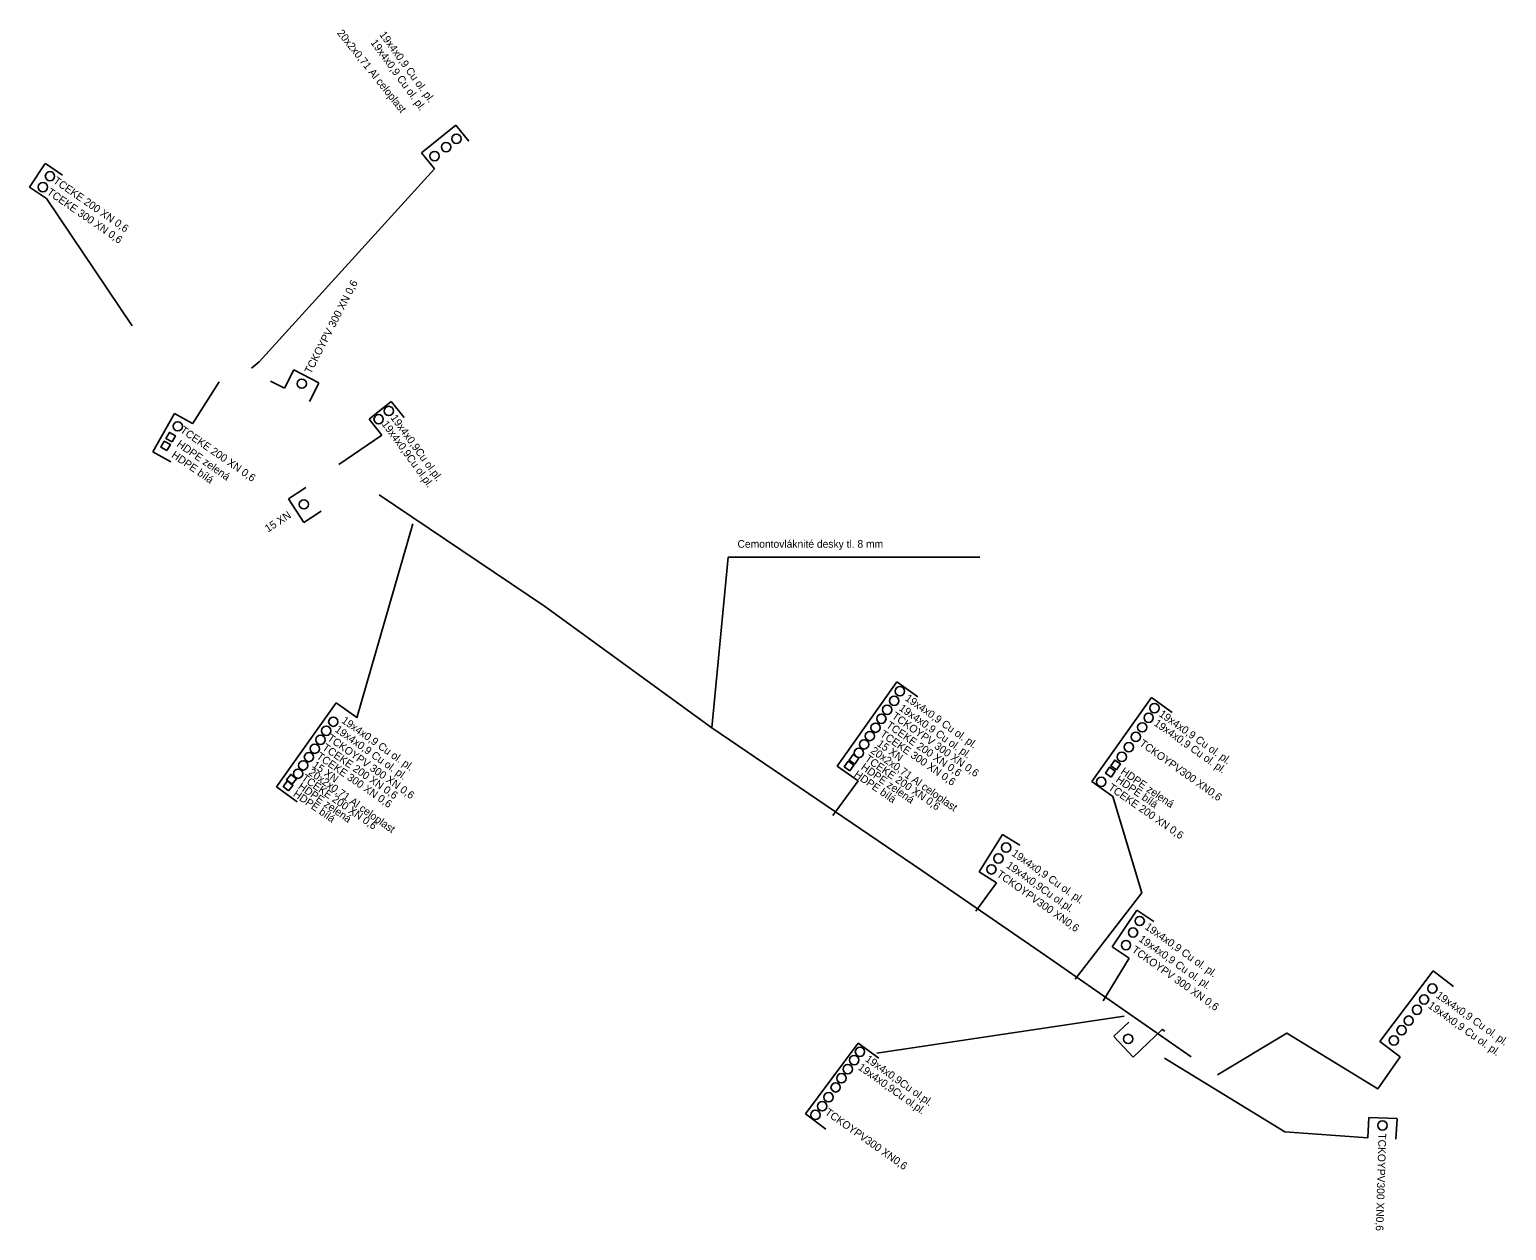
# Model space of a CAD drawing. Extents: x -668939 to -668824, y -1128143 to -1128050.
import ezdxf

# ---------------------------------------------------------------- set-up
doc = ezdxf.new("R2010")
doc.units = 0
doc.layers.add('Vrstva 20', color=7, linetype='Continuous')
doc.layers.add('Vrstva 30', color=7, linetype='Continuous')

msp = doc.modelspace()

# ---------------------------------------------------------------- linework, layer by layer
at = {"layer": 'Vrstva 20'}
for p, q in [((-668905.91, -1128057.19), (-668908.6, -1128059.34)), ((-668904.91, -1128058.43), (-668905.91, -1128057.19)), ((-668908.6, -1128059.34), (-668907.6, -1128060.59)), ((-668937.98, -1128060.18), (-668939.21, -1128062.02)), ((-668936.64, -1128061.08), (-668937.97, -1128060.19)), ((-668939.21, -1128062.02), (-668937.87, -1128062.91)), ((-668919.3, -1128077.73), (-668920.4, -1128077.18)), ((-668918.57, -1128076.3), (-668919.3, -1128077.73)), ((-668916.61, -1128077.31), (-668918.57, -1128076.3)), ((-668917.35, -1128078.75), (-668916.62, -1128077.32)), ((-668910.97, -1128078.75), (-668912.69, -1128080.13)), ((-668909.96, -1128080.01), (-668910.96, -1128078.76)), ((-668912.69, -1128080.13), (-668911.69, -1128081.38)), ((-668911.69, -1128081.38), (-668915.05, -1128083.68)), ((-668917.64, -1128085.47), (-668918.98, -1128086.35)), ((-668918.99, -1128086.36), (-668917.78, -1128088.2)), ((-668917.78, -1128088.2), (-668916.44, -1128087.33)), ((-668852.75, -1128118.47), (-668854.67, -1128121.34)), ((-668851.42, -1128119.36), (-668852.75, -1128118.47)), ((-668855.38, -1128125.56), (-668853.34, -1128122.23)), ((-668854.67, -1128121.34), (-668853.34, -1128122.23)), ((-668829.62, -1128123.22), (-668833.78, -1128128.72)), ((-668828.02, -1128124.43), (-668829.62, -1128123.22)), ((-668873.06, -1128129.65), (-668853.74, -1128126.74)), ((-668853.39, -1128127.22), (-668854.55, -1128128.32)), ((-668874.5, -1128128.85), (-668878.63, -1128134.37)), ((-668872.9, -1128130.04), (-668874.5, -1128128.85)), ((-668854.56, -1128128.33), (-668853.04, -1128129.94)), ((-668853.04, -1128129.94), (-668851.88, -1128128.83)), ((-668833.78, -1128128.72), (-668832.19, -1128129.93)), ((-668878.63, -1128134.37), (-668877.03, -1128135.57)), ((-668834.65, -1128134.65), (-668834.72, -1128136.25)), ((-668832.44, -1128134.75), (-668834.65, -1128134.65)), ((-668832.52, -1128136.36), (-668832.44, -1128134.77))]:
    msp.add_line(p, q, dxfattribs=at)
for points in [[(-668907.6, -1128060.59), (-668921.27, -1128075.66), (-668921.87, -1128076.16)], [(-668851.88, -1128128.83), (-668850.78, -1128127.78), (-668850.58, -1128127.92)], [(-668846.45, -1128131.33), (-668841.05, -1128128.07), (-668833.94, -1128132.43), (-668832.19, -1128129.93)], [(-668834.72, -1128136.25), (-668841.19, -1128135.77), (-668850.6, -1128130.02)]]:
    msp.add_lwpolyline(points, dxfattribs=at)
for centre in [(-668906.68, -1128058.9), (-668905.88, -1128058.25), (-668907.58, -1128059.6), (-668937.61, -1128061.17), (-668938.16, -1128062.02), (-668917.95, -1128077.37), (-668911.16, -1128079.5), (-668911.95, -1128080.15), (-668917.79, -1128086.79), (-668853.05, -1128120.22), (-668852.53, -1128119.32), (-668853.6, -1128121.2), (-668829.68, -1128124.6), (-668830.33, -1128125.45), (-668831.53, -1128127.1), (-668830.88, -1128126.25), (-668853.43, -1128128.53), (-668832.08, -1128127.85), (-668874.37, -1128129.53), (-668832.68, -1128128.65), (-668874.82, -1128130.18), (-668875.82, -1128131.6), (-668875.32, -1128130.88), (-668876.82, -1128133.08), (-668876.27, -1128132.31), (-668877.32, -1128133.78), (-668877.85, -1128134.46), (-668833.58, -1128135.28)]:
    msp.add_circle(centre, 0.363, dxfattribs=at)
at = {"layer": 'Vrstva 30'}
for p, q in [((-668937.87, -1128062.91), (-668931.19, -1128072.86)), ((-668926.49, -1128080.5), (-668924.41, -1128077.22)), ((-668927.89, -1128079.69), (-668929.58, -1128082.7)), ((-668926.49, -1128080.47), (-668927.89, -1128079.69)), ((-668929.58, -1128082.7), (-668928.18, -1128083.48)), ((-668885.93, -1128104.24), (-668884.66, -1128090.92)), ((-668884.66, -1128090.92), (-668865.01, -1128090.92)), ((-668871.49, -1128100.65), (-668876.15, -1128107.22)), ((-668869.86, -1128101.81), (-668871.49, -1128100.65)), ((-668915.27, -1128102.28), (-668919.93, -1128108.85)), ((-668913.64, -1128103.44), (-668915.27, -1128102.28)), ((-668851.62, -1128101.87), (-668856.27, -1128108.44)), ((-668849.99, -1128103.03), (-668851.62, -1128101.87)), ((-668876.15, -1128107.22), (-668874.51, -1128108.37)), ((-668876.48, -1128111.09), (-668874.51, -1128108.37)), ((-668856.27, -1128108.44), (-668854.64, -1128109.59)), ((-668919.93, -1128108.85), (-668918.3, -1128110.01)), ((-668863.23, -1128112.56), (-668865.07, -1128115.48)), ((-668861.88, -1128113.41), (-668863.23, -1128112.56)), ((-668865.07, -1128115.48), (-668863.71, -1128116.33)), ((-668863.71, -1128116.33), (-668865.32, -1128118.56))]:
    msp.add_line(p, q, dxfattribs=at)
for points in [[(-668928.48, -1128082.6), (-668928.95, -1128082.34), (-668928.69, -1128081.86), (-668928.21, -1128082.13)], [(-668928.08, -1128081.92), (-668928.56, -1128081.65), (-668928.29, -1128081.17), (-668927.82, -1128081.44)], [(-668875.16, -1128107.59), (-668875.6, -1128107.28), (-668875.29, -1128106.83), (-668874.84, -1128107.15)], [(-668874.77, -1128107.07), (-668875.22, -1128106.76), (-668874.9, -1128106.31), (-668874.46, -1128106.62)], [(-668854.75, -1128108.08), (-668855.2, -1128107.78), (-668854.9, -1128107.32), (-668854.45, -1128107.62)], [(-668854.33, -1128107.51), (-668854.78, -1128107.21), (-668854.48, -1128106.76), (-668854.03, -1128107.06)], [(-668918.98, -1128109.15), (-668919.4, -1128108.81), (-668919.07, -1128108.39), (-668918.64, -1128108.73)], [(-668918.37, -1128108.21), (-668918.7, -1128108.64), (-668919.14, -1128108.31), (-668918.81, -1128107.88)]]:
    msp.add_lwpolyline(points, close=True, dxfattribs=at)
for points in [[(-668911.9, -1128086.06), (-668899, -1128094.75), (-668885.93, -1128104.24), (-668869.54, -1128115.37), (-668859.89, -1128122.02), (-668848.5, -1128129.93)], [(-668913.66, -1128103.46), (-668909.28, -1128088.3)], [(-668854.64, -1128109.59), (-668852.37, -1128117.13), (-668857.58, -1128123.86)]]:
    msp.add_lwpolyline(points, dxfattribs=at)
for centre in [(-668927.63, -1128080.7), (-668871.25, -1128101.38), (-668872.25, -1128102.83), (-668871.7, -1128102.13), (-668851.38, -1128102.7), (-668915.49, -1128103.76), (-668873.15, -1128104.23), (-668872.7, -1128103.53), (-668852.33, -1128104.2), (-668851.83, -1128103.45), (-668916.49, -1128105.17), (-668916.04, -1128104.47), (-668873.6, -1128104.88), (-668852.83, -1128104.95), (-668917.39, -1128106.52), (-668916.94, -1128105.87), (-668874.45, -1128106.19), (-668874.05, -1128105.53), (-668853.93, -1128106.51), (-668853.38, -1128105.75), (-668917.84, -1128107.17), (-668918.24, -1128107.82), (-668855.53, -1128108.46), (-668863.56, -1128114.44), (-668862.96, -1128113.59), (-668864.11, -1128115.29)]:
    msp.add_circle(centre, 0.363, dxfattribs=at)

# ---------------------------------------------------------------- texts
at = {"layer": 'Vrstva 20'}
for s, rotation, p in [('20x2x0,71 Al celoplast', 308.6806, (-668915.23, -1128050.01)), ('19x4x0,9 Cu ol. pl.', 306.0633, (-668912.61, -1128050.75)), ('19x4x0,9 Cu ol. pl.', 306.0633, (-668911.92, -1128050.12)), ('TCEKE 200 XN 0,6', 325.2888, (-668937.41, -1128061.66)), ('TCEKE 300 XN 0,6', 325.2888, (-668937.9, -1128062.54)), ('TCKOYPV 300 XN 0,6', 62.8314, (-668917.24, -1128076.65)), ('19x4x0,9Cu ol.pl.', 306.0633, (-668911.74, -1128080.53)), ('19x4x0,9Cu ol.pl.', 306.0633, (-668911.05, -1128080.04)), ('15 XN', 33.3013, (-668920.59, -1128089)), ('19x4x0,9 Cu ol. pl.', 324.6463, (-668852.18, -1128119.9)), ('TCKOYPV 300 XN 0,6', 324.6463, (-668853.2, -1128121.7)), ('19x4x0,9 Cu ol. pl.', 324.6463, (-668852.66, -1128120.85)), ('19x4x0,9 Cu ol. pl.', 324.6463, (-668830.07, -1128126.05)), ('19x4x0,9 Cu ol. pl.', 324.6463, (-668829.45, -1128125.25)), ('19x4x0,9Cu ol.pl.', 324.6463, (-668874.01, -1128130.22)), ('19x4x0,9Cu ol.pl.', 324.6463, (-668874.57, -1128130.87)), ('TCKOYPV300 XN0,6', 268.3207, (-668833.88, -1128135.89))]:
    msp.add_text(s, height=0.6, rotation=rotation, dxfattribs=at).set_placement(p)
at = {"layer": 'Vrstva 30'}
for s, rotation, p in [('TCEKE 200 XN 0,6', 325.2888, (-668927.5, -1128081.13)), ('HDPE zelená', 325.2888, (-668927.77, -1128082.22)), ('HDPE bílá', 325.2888, (-668928.18, -1128083.07)), ('19x4x0,9 Cu ol. pl.', 324.6463, (-668871.37, -1128102.82)), ('19x4x0,9 Cu ol. pl.', 324.6463, (-668870.9, -1128102.05)), ('19x4x0,9 Cu ol. pl.', 324.6463, (-668914.9, -1128103.79)), ('TCEKE 200 XN 0,6', 325.2888, (-668872.38, -1128104.16)), ('TCKOYPV 300 XN 0,6', 324.6463, (-668871.93, -1128103.44)), ('19x4x0,9 Cu ol. pl.', 324.6463, (-668851.47, -1128104)), ('19x4x0,9 Cu ol. pl.', 324.6463, (-668851.08, -1128103.28)), ('TCKOYPV 300 XN 0,6', 324.6463, (-668916.01, -1128105.17)), ('19x4x0,9 Cu ol. pl.', 324.6463, (-668915.42, -1128104.49)), ('TCEKE 300 XN 0,6', 325.2888, (-668872.85, -1128104.86)), ('TCKOYPV300 XN0,6', 324.6463, (-668852.6, -1128105.58)), ('TCEKE 300 XN 0,6', 325.2888, (-668916.85, -1128106.59)), ('TCEKE 200 XN 0,6', 325.2888, (-668916.4, -1128105.91)), ('20x2x0,71 Al celoplast', 324.6463, (-668873.59, -1128106.15)), ('15 XN', 324.6463, (-668873.09, -1128105.6)), ('15 XN', 324.6463, (-668917.18, -1128107.27)), ('HDPE zelená', 325.2888, (-668874.35, -1128107.44)), ('TCEKE 200 XN 0,6', 325.2888, (-668874.05, -1128106.78)), ('HDPE zelená', 325.2888, (-668854.07, -1128107.78)), ('HDPE zelená', 325.2888, (-668918.29, -1128108.94)), ('TCEKE 200 XN 0,6', 325.2888, (-668918.03, -1128108.29)), ('20x2x0,71 Al celoplast', 324.6463, (-668917.48, -1128107.84)), ('HDPE bílá', 325.2888, (-668874.89, -1128108.01)), ('TCEKE 200 XN 0,6', 325.2888, (-668855.04, -1128109.03)), ('HDPE bílá', 325.2888, (-668854.45, -1128108.41)), ('HDPE bílá', 325.2888, (-668918.68, -1128109.53)), ('19x4x0,9 Cu ol. pl.', 324.6463, (-668862.58, -1128114.16)), ('TCKOYPV300 XN0,6', 324.6463, (-668863.74, -1128115.8)), ('19x4x0,9Cu ol.pl.', 324.6463, (-668863, -1128115.1)), ('TCKOYPV300 XN0,6', 324.6463, (-668877.16, -1128134.38))]:
    msp.add_text(s, height=0.6, rotation=rotation, dxfattribs=at).set_placement(p)
msp.add_text('Cemontovláknité desky tl. 8 mm', height=0.6, dxfattribs=at).set_placement((-668883.93, -1128090.18))

doc.saveas('drawing.dxf')
